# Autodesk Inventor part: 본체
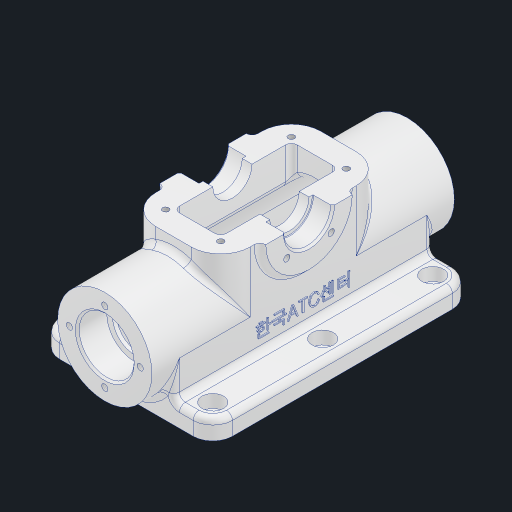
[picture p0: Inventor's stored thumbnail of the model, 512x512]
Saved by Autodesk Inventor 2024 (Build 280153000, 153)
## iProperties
Created: 2024-06
Part Number: 본체
Material: 알루미늄 6061
Document SubType Name: Modeling
Designer: kh_501
Density: 2.7 g/cm^3
Appearance: 알루미늄 - 평지
Mass: 551.648 g
Surface Area: 612.71 cm^2
Volume: 204.314 cm^3
Author: kh_501
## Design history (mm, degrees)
sketch "스케치1"
  geometry: L1 (-44, 66)-(44, 66); L2 (44, 66)-(44, -66); L3 (44, -66)-(-44, -66); L4 (-44, -66)-(-44, 66); L5 (-44, 66)-(44, -66); L6 (44, 66)-(-44, -66); 1 further point
  constraints: 12 end point, 2 midpoint, 2 parallel, 1 horizontal, 1 perpendicular
  dimensions: "d0" = 88 distance of L2.end L3.end; "d1" = 132 distance of L1.end L2.end
extrude "돌출1" new body sketch "스케치1" distance "d2" = 10; taper "d3" = 0 deg
sketch "스케치2"
  geometry: L1 (52, 77)-(28, 77); L2 (28, 77)-(28, -77); L3 (28, -77)-(52, -77); L4 (52, -77)-(52, 77); L5 (0, -66)-(0, 66) reference; 3 further points
  constraints: 8 end point, 2 midpoint, 2 parallel, 1 horizontal, 1 horizontal alignment, 1 perpendicular
  dimensions: "d4" = 28 distance from line of L5 L1.end; "d5" = 48 diameter of L4 L2; "d6" = 154 distance between parallel lines of L3 L1
revolve "회전1" sketch "스케치2" stored, may be unused: angle "d7" = 90 deg
node "작업 평면1"
sketch "스케치4"
  geometry: L1 (-15.875, 66)-(-44, 66) reference; L2 (44, 66)-(15.875, 66) reference; L3 (15.875, -66)-(44, -66) reference; L4 (-44, -66)-(-15.875, -66) reference; L5 (-24, -77)-(-24, 77) reference; L6 (24, -77)-(24, 77) reference; L7 (-24, 66)-(24, 66); L8 (24, 66)-(24, -66); L9 (24, -66)-(-24, -66); L10 (-24, -66)-(-24, 66); 7 further points
  constraints: 8 end point, 4 point on line, 2 parallel, 1 horizontal, 1 perpendicular
extrude "돌출3" join sketch "스케치4" stored distance "d14" = 10; taper "d15" = 0 deg
sketch "스케치3"
  geometry: L1 (-24, 42)-(24, 42); L2 (24, 42)-(24, -42); L3 (24, -42)-(-24, -42); L4 (-24, -42)-(-24, 42); L5 (-24, 42)-(24, -42); L6 (24, 42)-(-24, -42); 1 further point
  constraints: 12 end point, 2 midpoint, 2 parallel, 1 horizontal, 1 perpendicular
  dimensions: "d10" = 84 distance of L1.end L2.end; "d11" = 48 distance of L2.end L3.end
extrude "돌출2" join sketch "스케치3" stored distance "d12" = 10; taper "d13" = 0 deg
sketch "스케치5"
  geometry: L1 (0, -28)-(0, 28); L2 (18, -28)-(18, 28); L3 (-18, 28)-(-18, -28); L4 (-24, 59)-(-24, 28) reference; L5 (-24, 10)-(-24, 28) reference; L6 (24, 10)-(24, 28) reference; L7 (24, 59)-(24, 28) reference; L8 (44, 0)-(-44, 0) reference; A1 r 18 centre (0, -28) between (-18, -28) and (18, -28); A2 r 18 centre (0, 28) between (18, 28) and (-18, 28); 3 further points
  constraints: 8 end point, 4 point on circle, 4 tangent, 2 centre point, 1 midpoint, 1 parallel, 1 vertical
  dimensions: "d16" = 6 distance between parallel lines of L5 L3; "d17" = 28 distance from line of L8 L1.end
extrude "돌출4" cut sketch "스케치5" stored distance "d18" = 120; taper "d19" = 0 deg
sketch "스케치6"
  geometry: L1 (46, 60)-(28, 60) reference; L2 (28, 60)-(0, 60) reference; L3 (4, 77)-(52, 77) reference; L4 (28, -60)-(46, -60) reference; L5 (0, -60)-(28, -60) reference; L6 (4, -77)-(52, -77) reference; L7 (28, 77)-(28, 60); L8 (28, -77)-(28, -60); L9 (42, 77)-(42, 62); L10 (42, 62)-(39, 62); L11 (39, 62)-(39, 60); L12 (42, -77)-(42, -62); L13 (42, -62)-(39, -62); L14 (39, -62)-(39, -60); 1 further point
  constraints: 16 end point, 4 point on line, 3 perpendicular, 3 vertical, 2 midpoint, 1 collinear, 1 horizontal
  dimensions: "d20" = 28 diameter of L9 L7; "d21" = 22 diameter of L11 L7; "d22" = 15 distance of L9.start L9.end; "d23" = 28 diameter of L12 L8; "d24" = 22 diameter of L14 L8; "d25" = 15 distance of L12.start L12.end
revolve "회전2" sketch "스케치6" stored, may be unused: angle "d26" = 90 deg
node "작업 평면2"
sketch "스케치7"
  geometry: L1 (59, -42)-(59, 42) reference; C1 r 22 at (59, 0); 3 further points
  constraints: 1 centre point, 1 midpoint
  dimensions: "d27" = 44 diameter of C1
extrude "돌출5" join sketch "스케치7" stored distance "d28" = 54; taper "d29" = 0 deg
sketch "스케치8"
  geometry: L1 (12, -30)-(-12, -30); L2 (-12, -30)-(-12, 30); L3 (-12, 30)-(12, 30); L4 (12, 30)-(12, -30); L5 (12, -30)-(-12, 30); L6 (-12, -30)-(12, 30); 1 further point
  constraints: 12 end point, 2 midpoint, 2 parallel, 1 horizontal, 1 perpendicular
  dimensions: "d30" = 24 distance of L2.end L3.end; "d31" = 60 distance of L1.end L2.end
extrude "돌출6" cut sketch "스케치8" extent not by distance; stored distance "d32" = 0; taper "d33" = 0 deg
sketch "스케치9"
  geometry: L1 (22, 59)-(-22, 59) reference; A1 r 22 centre (0, 59) between (-22, 59) and (22, 59) reference; 3 further points
  constraints: 1 coincident
hole "구멍1" sketch "스케치9" at (0, 59) diameter "d34" = 20; stored, may be unused: countersink angle "d38" = 90 deg, drill point angle "d40" = 118 deg; dims "d35" = 6, "d36" = 24, "d37" = 10, "d39" = 8
sketch "스케치11"
  geometry: L1 (14, -32)-(-14, -32); L2 (-14, -32)-(-14, 32); L3 (-14, 32)-(14, 32); L4 (14, 32)-(14, -32); L5 (14, -32)-(-14, 32); L6 (-14, -32)-(14, 32); 5 further points
  constraints: 12 end point, 4 coincident, 2 midpoint, 2 parallel, 1 horizontal, 1 perpendicular
  dimensions: "d48" = 28 distance of L2.end L3.end; "d49" = 64 distance of L1.end L2.end
hole "구멍3" sketch "스케치11" at (-14, -32), (-14, 32), (14, 32), (14, -32) diameter "d50" = 3.242; stored, may be unused: countersink angle "d54" = 90 deg, drill point angle "d56" = 118 deg; dims "d51" = 8, "d52" = 24, "d53" = 10, "d55" = 10
sketch "스케치12"
  geometry: L1 (0, 59)-(0, 43); L2 (0, 59)-(-11.314, 47.686); L3 (0, 59)-(11.314, 47.686); A1 r 16 centre (0, 59) between (0, 43) and (-11.314, 47.686); A2 r 22 centre (0, 59) between (-22, 59) and (22, 59) reference; 4 further points
  constraints: 6 end point, 4 coincident, 3 point on circle, 1 centre point, 1 perpendicular, 1 vertical
  dimensions: "d57" = 32 diameter of A1; "d58" = 45 deg angle of L1 L2
hole "구멍4" sketch "스케치12" at (-11.314, 47.686), (11.314, 47.686) diameter "d59" = 3.242; stored, may be unused: countersink angle "d63" = 90 deg, drill point angle "d65" = 118 deg; dims "d60" = 8, "d61" = 4, "d62" = 2, "d64" = 10
sketch "스케치13" dims "d66" = 36
  geometry: L1 (0, 0)-(0, 18); C1 r 24 at (0, 0) reference; 2 further points
  constraints: 2 coincident, 2 end point, 1 vertical, 1 vertical alignment, 2 other
hole "구멍5" sketch "스케치13" at (0, 18) diameter "d67" = 3.242; stored, may be unused: countersink angle "d71" = 90 deg, drill point angle "d73" = 118 deg; dims "d68" = 8, "d69" = 4, "d70" = 2, "d72" = 10
sketch "스케치14"
  geometry: L1 (34, -56)-(-34, -56); L2 (-34, -56)-(-34, 56); L3 (-34, 56)-(34, 56); L4 (34, 56)-(34, -56); L5 (34, -56)-(-34, 56); L6 (-34, -56)-(34, 56); 7 further points
  constraints: 12 end point, 4 coincident, 4 midpoint, 2 parallel, 1 horizontal, 1 perpendicular
  dimensions: "d77" = 68 distance of L2.end L3.end; "d78" = 112 distance of L1.end L2.end
hole "구멍6" sketch "스케치14" at (-34, -56), (-34, 56), (34, 56), (34, -56), (-34, 0), (34, 0) diameter "d79" = 6.6; stored, may be unused: countersink angle "d83" = 90 deg, drill point angle "d85" = 118 deg; dims "d80" = 8, "d81" = 11, "d82" = 6.6, "d84" = 10
fillet "모깎기1" dims "d86" = 10
fillet "모깎기2" dims "d87" = 3
fillet "모깎기3" dims "d88" = 3
fillet "모깎기4" dims "d89" = 3
fillet "모깎기5" dims "d90" = 15
fillet "모깎기6" dims "d91" = 3
fillet "모깎기7" dims "d92" = 3
fillet "모깎기8" dims "d93" = 3
fillet "모깎기9" dims "d95" = 3
chamfer "모따기1" distance "d96" = 1; stored, may be unused: second distance "d97" = 2, angle "d98" = 45 deg
fillet "모깎기10" dims "d99" = 0.3
fillet "모깎기11" dims "d100" = 3
sketch "스케치15"
  geometry: L1 (7, -13)-(119, -13) reference; 3 further points
  constraints: 1 midpoint, 1 vertical alignment, 1 other
  dimensions: "d101" = 20 distance from line of L1 point (63, 7)
feature "엠보싱1" sketch "스케치15" dims "d102" = 0.5, "d103" = 0
chamfer "모따기2" distance "d104" = 1; stored, may be unused: second distance "d105" = 2, angle "d106" = 45 deg
node "솔리드1"
mirror "미러3"
mirror "미러1"
mirror "미러4"
pattern_circular "원형 패턴1" dims angle "d75" = 360 deg
mirror "미러2"
feature "A9D066F2-1C7D-4E18-AEED-F7BC21143FA4" dims "d79" = 6.6, "d80" = 8, "d81" = 11, "d82" = 6.6, "d83" = 90 deg, "d84" = 10, "d85" = 118 deg
other parameters: "d8" = 59, "d94" = 27
